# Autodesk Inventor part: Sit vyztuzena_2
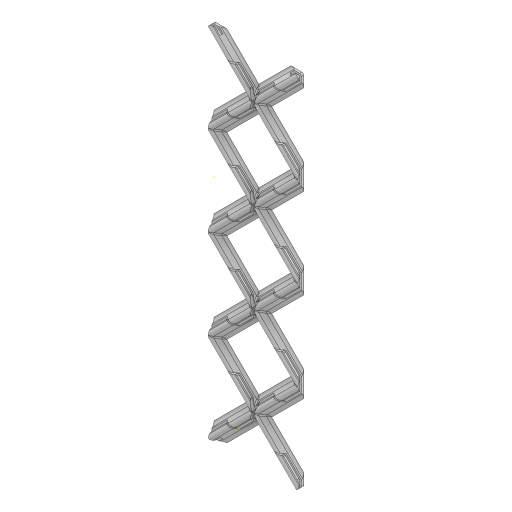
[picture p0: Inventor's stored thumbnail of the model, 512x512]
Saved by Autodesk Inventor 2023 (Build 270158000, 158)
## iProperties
Created: 2025-03
Part Number: Sit vyztuzena_2
Material: Všeobecné
Document SubType Name: Modeling
Designer: tomik
Density: 1 g/cm^3
Appearance: Výchozí
Author: tomik
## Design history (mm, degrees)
sketch "Náčrt1"
  geometry: L1 (0, 0)-(211.67, 0); L2 (0, 0)-(200, 200)
  constraints: 4 end point, 1 horizontal
  dimensions: "d1" = 45 deg angle of L1 L2; "d2" = 200 distance from line of L2.end L1
node "Pracovní rovina2"
sketch "Náčrt2"
  geometry: L1 (0, 0)-(0, 13.004); L2 (0, 0)-(-15.85, 0); L3 (0, 0)-(-4, 0); L4 (-3.268, 0.732)-(0, 4); L5 (0, 0)-(15.85, 0); L6 (0, 0)-(4, 0); L7 (3.268, 0.732)-(0, 4); L8 (0, 0)-(15.85, 0); L9 (5.036, 0)-(-5.036, 0); A1 r 2.5 centre (-5.036, 2.5) between (-5.036, 0) and (-3.268, 0.732); A2 r 2.5 centre (5.036, 2.5) between (3.268, 0.732) and (5.036, 0); 2 further points
  constraints: 18 end point, 5 point on line, 5 symmetric about line, 4 point on circle, 4 tangent, 2 centre point, 1 collinear, 1 horizontal, 1 vertical, 1 other
  dimensions: "d3" = 4 distance of L1.start L3.end; "d4" = 4 distance of L4.end L1.start; "d5" = 5 diameter of A1; "d6" = 5.03553 distance from line of L9.end L1
extrude "Vysunutí1" new body sketch "Náčrt2" distance "d7" = 200; taper "d8" = 0 deg
node "Pracovní rovina6"
fillet "Zaoblení3" dims "d14" = 2
mirror "Zrcadlit3"
node "Pracovní rovina10"
  node "Pracovní rovina9"
node "Pracovní rovina11"
pattern_linear "Obdélníkové pole1"
sketch "Náčrt3"
  geometry: 1 further point
sketch "Náčrt4"
  geometry: L1 (-30.32, -10.071)-(-30.32, 0) reference; L2 (-30.32, 0)-(0, 0) reference; L3 (10.071, -40.391)-(10.071, -10.071) reference; L4 (0, -40.391)-(10.071, -40.391) reference; L5 (-30.32, -3.621)-(-30.32, -6.45) reference; L6 (-30.32, -5.036)-(5.036, -40.391); L7 (-30.32, -5.036)-(111.102, 136.386); L8 (111.102, 136.386)-(146.457, 101.03); L9 (146.457, 101.03)-(5.036, -40.391); L10 (40.391, 415.738)-(-248.096, 101.03); L11 (-248.096, 101.03)-(128.779, -294.975); L12 (128.779, -294.975)-(406.838, 40.162); L13 (406.838, 40.162)-(40.391, 415.738); 7 further points
  constraints: 16 end point, 2 perpendicular, 1 coincident, 1 midpoint
  dimensions: "d23" = 200 distance of L6.start L7.end; "d24" = 50 distance of L7.end L8.end
extrude "Vysunutí2" cut sketch "Náčrt4" distance "d25" = 200; taper "d26" = 0 deg
fillet "Zaoblení5" dims "d27" = 1
fillet "Zaoblení6" dims "d28" = 1
sketch "Náčrt5"
  geometry: L1 (3.268, 0.732)-(1.414, 2.586) reference; L2 (0, 0)-(0, 7.359); L3 (0, 0)-(6.319, 0); L4 (5.036, 0)-(-5.036, 0) reference; L5 (1.8, 1.2)-(2.8, 1.2); L6 (2.8, 1.2)-(2.8, 2.2); L7 (2.8, 2.2)-(1.8, 2.2); L8 (1.8, 2.2)-(1.8, 1.2); 3 further points
  constraints: 12 end point, 2 parallel, 1 collinear, 1 horizontal, 1 midpoint, 1 perpendicular, 1 vertical
  dimensions: "d30" = 2.8 distance between parallel lines of L6 L2; "d31" = 1.2 distance between parallel lines of L5 L3; "d32" = 1 distance between parallel lines of L6 L8; "d33" = 1 distance from line of L7 point (2.3, 1.2)
extrude "Vysunutí3" cut sketch "Náčrt5" distance "d34" = 15; taper "d35" = 0 deg
node "Pracovní rovina14"
node "Pracovní rovina16"
  node "Pracovní rovina15"
pattern_linear "Obdélníkové pole2" dims "d40" = 50
mirror "Zrcadlit6"
node "Pracovní rovina19"
mirror "Zrcadlit7"
node "Pracovní rovina21"
sketch "Náčrt9"
  geometry: L1 (-50, 1.2)-(-50, 2.2) reference; L2 (-50, 2.2)-(-40.666, 2.2) reference; L3 (-50, 1.2)-(-40.666, 1.2) reference; L4 (-49, 2.2)-(-49, 1.2); 1 further point
  constraints: 2 end point, 2 point on line, 1 perpendicular
  dimensions: "d47" = 1 distance between parallel lines of L4 L1
extrude "Vysunutí5" cut sketch "Náčrt9" stored distance "d48" = 10; taper "d49" = 0 deg
mirror "Zrcadlit8"
node "Pracovní rovina22"
mirror "Zrcadlit9"
node "Pracovní rovina23"
mirror "Zrcadlit11"
sketch "Náčrt10"
  geometry: L1 (-1.8, 1.2)-(-2.8, 1.2); L2 (-2.8, 1.2)-(-2.8, 2.2); L3 (-2.8, 2.2)-(-1.8, 2.2); L4 (-1.8, 2.2)-(-1.8, 1.2); L5 (-5.036, 0)-(5.036, 0) reference; L6 (0, 0)-(0, 4.936); L7 (0, 0)-(-0.148, 0); 1 further point
  constraints: 12 end point, 2 parallel, 1 horizontal, 1 midpoint, 1 perpendicular, 1 point on line, 1 vertical
  dimensions: "d55" = 1.2 distance between parallel lines of L5 L1; "d56" = 1.8 distance between parallel lines of L4 L6; "d57" = 1 distance between parallel lines of L2 L4; "d58" = 1 distance between parallel lines of L3 L1
extrude "Vysunutí6" cut sketch "Náčrt10" distance "d59" = 32; taper "d60" = 0 deg
sketch "Náčrt11"
  geometry: 1 further point
mirror "Zrcadlit12"
sketch "Náčrt12"
  geometry: 1 further point
node "Pracovní rovina25"
mirror "Zrcadlit13"
fillet "Zaoblení7" dims "d70" = 1
node "Pracovní rovina31"
sketch "Náčrt20"
  geometry: L1 (0, 0)-(-7.595, 0); L2 (-1.2, -1.8)-(-1.2, -2.8) reference; L3 (-2.2, -1.8)-(-1.2, -1.8) reference; L4 (-1.2, 1.8)-(-1.2, 2.8); L5 (-2.2, 1.8)-(-1.2, 1.8); L6 (-2.586, 1.414)-(-0.732, 3.268) reference
  constraints: 6 end point, 3 symmetric about line, 1 horizontal
extrude "Vysunutí12" cut sketch "Náčrt20" distance "d79" = 11; taper "d80" = 0 deg
mirror "Zrcadlit15"
pattern_linear "Obdélníkové pole3" dims "d83" = 50
mirror "Zrcadlit16"
sketch "Náčrt23"
  geometry: 1 further point
sketch "Náčrt24"
  geometry: L1 (1.293, 53.838)-(8.627, 61.172) reference; L2 (8.627, 62.587)-(9.127, 62.087) reference; L3 (8.627, 61.172)-(9.334, 61.879); L4 (8.834, 61.379)-(1.293, 53.838) reference; L5 (9.334, 61.879)-(9.127, 62.087); L6 (8.627, 62.587)-(8.627, 61.172); 1 further point
  constraints: 6 end point, 1 collinear, 1 perpendicular, 1 vertical
extrude "Vysunutí14" cut sketch "Náčrt24" stored distance "d89" = 15; taper "d90" = 0 deg
node "Pracovní rovina32"
mirror "Zrcadlit18"
mirror "Zrcadlit19"
sketch "Náčrt25"
  geometry: L1 (9.334, 11.879)-(8.627, 12.587) reference; L2 (15.415, 11.455)-(14.708, 12.162) reference; L3 (9.334, 11.879)-(15.415, 11.455); L4 (8.627, 12.587)-(14.708, 12.162); L5 (22.486, 19.94)-(23.193, 19.233) reference; L6 (26.807, 30.767)-(34.585, 38.545) reference; L7 (22.486, 19.94)-(26.807, 30.767); L8 (35.292, 37.838)-(27.514, 30.06) reference; L9 (23.193, 19.233)-(27.514, 30.06); L10 (27.514, 30.06)-(26.807, 30.767) reference; L11 (35.292, 37.838)-(34.585, 38.545) reference; L12 (41.373, 37.413)-(40.666, 38.121) reference; L13 (35.292, 37.838)-(41.373, 37.413); L14 (34.585, 38.545)-(40.666, 38.121); 1 further point
  constraints: 12 end point
extrude "Vysunutí15" cut sketch "Náčrt25" stored distance "d92" = 10; taper "d93" = 0 deg
mirror "Zrcadlit20"
pattern_linear "Obdélníkové pole5"
fillet "Zaoblení9" dims "d97" = 1
pattern_linear "Obdélníkové pole6" dims "d100" = 50
sketch "Náčrt26"
  geometry: L1 (9.788, -134.193)-(15.415, -134.585) reference; 1 further point
sketch "Náčrt27"
  geometry: L1 (1.8, 1.2)-(2.8, 1.2) reference; L2 (1.8, 2.2)-(1.8, 1.2) reference; L3 (2.8, 1.2)-(1.414, 2.586) reference; L4 (0, 0)-(0, 4); L5 (-1.8, 1.2)-(-2.8, 1.2); L6 (-1.8, 2.2)-(-1.8, 1.2); L7 (-2.8, 1.2)-(-1.414, 2.586)
  constraints: 8 end point, 4 symmetric about line, 1 vertical
extrude "Vysunutí16" cut sketch "Náčrt27" distance "d101" = 6; taper "d102" = 0 deg
sketch "Náčrt28"
  geometry: L1 (0, 0)-(0, 1) reference; L2 (-4.2, 0)-(-1, 0) reference; L3 (0, 0)-(-1, 0); L4 (-1, 0)-(-1, 1); L5 (0, 1)-(-4.2, 1) reference; L6 (-1, 1)-(1.901, 1); L7 (1.901, 1)-(1.901, 0); L8 (1.901, 0)-(0, 0); 2 further points
  constraints: 10 end point, 3 perpendicular, 2 point on line, 1 collinear, 1 horizontal
extrude "Vysunutí17" cut sketch "Náčrt28" distance "d104" = 6; taper "d105" = 0 deg
fillet "Zaoblení10" dims "d106" = 1
mirror "Zrcadlit21"
mirror "Zrcadlit22"
fillet "Zaoblení11" dims "d107" = 1
fillet "Zaoblení12" dims "d108" = 1
fillet "Zaoblení13" dims "d109" = 1
fillet "Zaoblení14" dims "d110" = 1
node "Těleso1"
node "Pracovní rovina24"
node "Pracovní rovina26"
node "Pracovní rovina33"
node "Pracovní rovina34"
node "Pracovní rovina35"
node "Pracovní rovina36"
node "Pracovní rovina37"
node "Pracovní rovina38"
node "Pracovní rovina39"
other parameters: "d11" = 25, "d18" = 25, "d50" = 25, "d51" = 25, "d63" = 5, "d78" = -4
